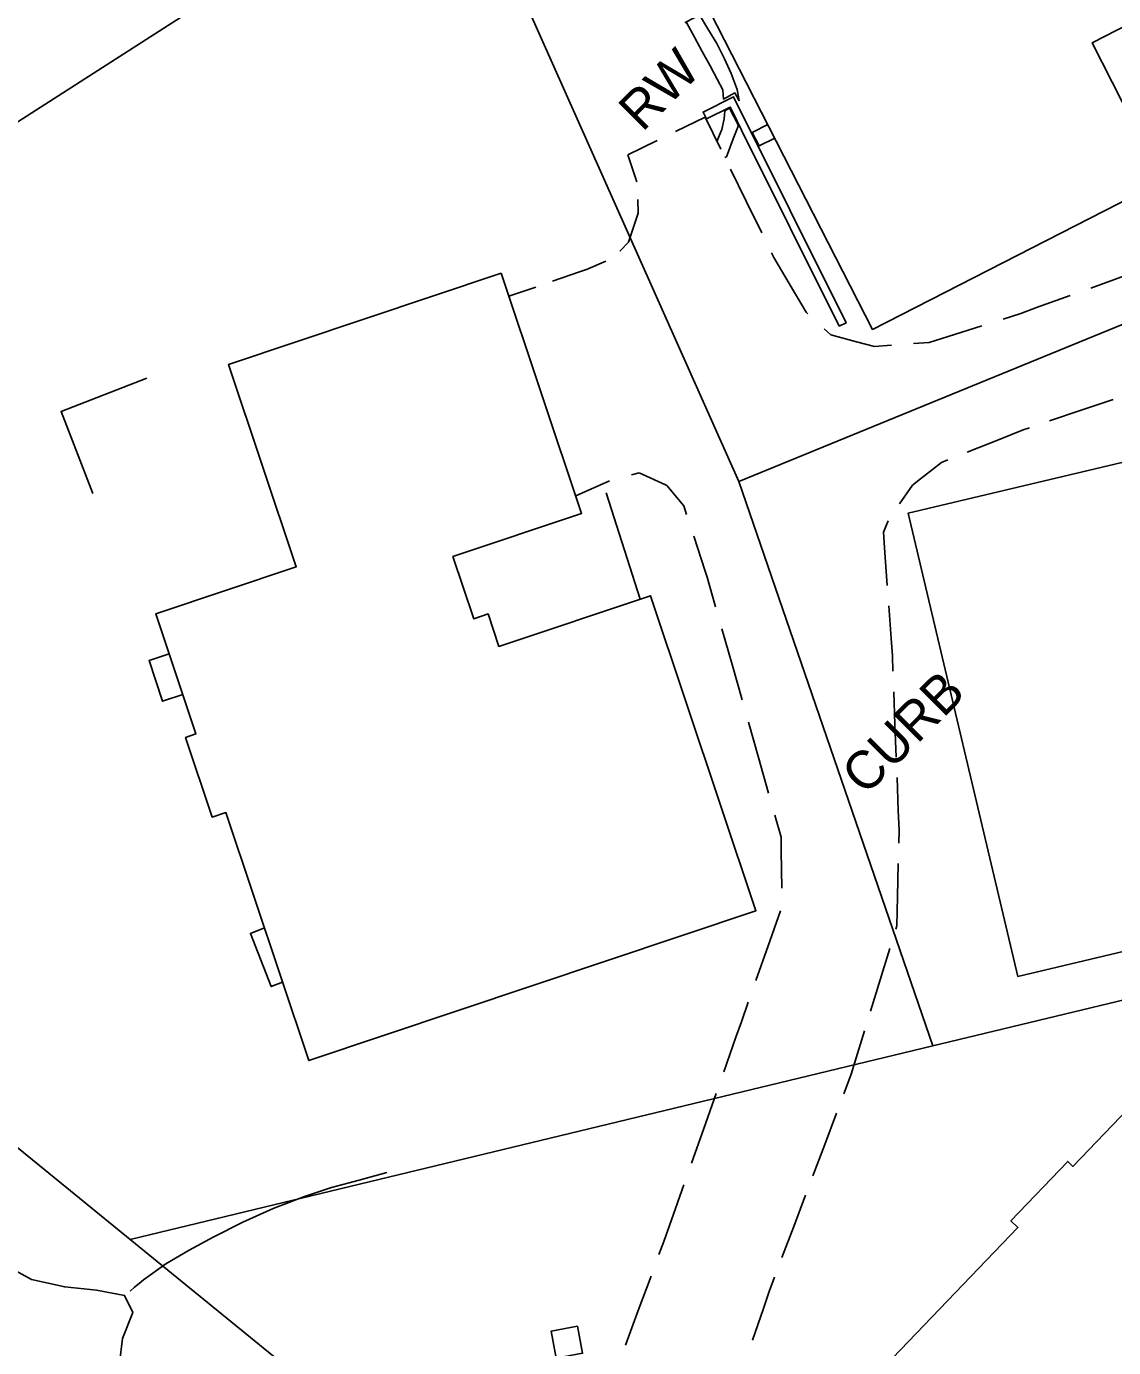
# Model space of a CAD drawing. Extents: x 2443269 to 2494951, y 591171 to 622130.
# Drawn here: x 2462063.7 to 2462180.8, y 603685.7 to 603828 of the extents above; entities that cross this region are included whole.
import ezdxf

# ---------------------------------------------------------------- set-up
doc = ezdxf.new("R2010")
doc.units = 0
for name, color, linetype in [('SURVEY - DRAINAGE - Natural Features', 7, 'Continuous'), ('SURVEY - NON-TRANSPORTATION - Buildings', 7, 'Continuous'), ('SURVEY - NON-TRANSPORTATION - Features', 7, 'Continuous'), ('SURVEY - NON-TRANSPORTATION - Features Text', 7, 'Continuous'), ('SURVEY - PROPERTY - Property Lines', 7, 'Continuous'), ('SURVEY - TRANSPORTATION - Features', 7, 'Continuous'), ('SURVEY - TRANSPORTATION - Features Text', 7, 'Continuous')]:
    doc.layers.add(name, color=color, linetype=linetype)

msp = doc.modelspace()

# ---------------------------------------------------------------- linework, layer by layer
at = {"layer": 'SURVEY - DRAINAGE - Natural Features'}
for points in [[(2462102.49, 603704.548), (2462099.514, 603703.727), (2462096.542, 603702.904), (2462093.612, 603701.962), (2462090.266, 603700.657), (2462086.981, 603699.19), (2462083.776, 603697.569), (2462081.194, 603696.175), (2462078.668, 603694.679), (2462076.279, 603692.989), (2462075.791, 603692.589), (2462075.308, 603692.176), (2462074.826, 603691.766)], [(2462073.688, 603684.01), (2462074.016, 603686.644), (2462075.115, 603689.466), (2462074.226, 603691.3), (2462071.204, 603691.861), (2462067.785, 603692.205), (2462064.209, 603693.025), (2462061.476, 603694.508)]]:
    msp.add_lwpolyline(points, dxfattribs=at)
at = {"layer": 'SURVEY - NON-TRANSPORTATION - Buildings'}
for points in [[(2462189.731, 603883.675), (2462200.446, 603862.74), (2462202.273, 603863.675), (2462218.467, 603832.031), (2462194.373, 603819.698), (2462187.585, 603832.963), (2462181.614, 603829.905), (2462182.464, 603828.248), (2462178.52, 603826.231), (2462186.132, 603811.358), (2462154.875, 603795.361), (2462131.712, 603840.624), (2462171.443, 603860.958), (2462169.124, 603865.489), (2462174.439, 603868.209), (2462171.342, 603874.262)], [(2462114.836, 603801.434), (2462123.504, 603775.538), (2462109.632, 603770.896), (2462111.873, 603764.197), (2462113.418, 603764.715), (2462114.593, 603761.211), (2462130.932, 603766.68), (2462142.296, 603732.733), (2462094.091, 603716.598), (2462085.151, 603743.307), (2462083.688, 603742.819), (2462080.81, 603751.411), (2462081.926, 603751.785), (2462077.595, 603764.721), (2462092.743, 603769.79), (2462085.443, 603791.595)], [(2462230.987, 603788.547), (2462239.091, 603754.347), (2462226.033, 603751.254), (2462225.085, 603755.25), (2462216.62, 603753.245), (2462220.292, 603737.746), (2462206.358, 603734.446), (2462206.588, 603733.478), (2462198.533, 603731.569), (2462198.369, 603732.258), (2462170.511, 603725.657), (2462158.691, 603775.558), (2462192.798, 603783.639), (2462196.712, 603767.12), (2462200.472, 603768.012), (2462200.912, 603766.158), (2462207.877, 603767.809), (2462204.452, 603782.261)], [(2462187.359, 603669.479), (2462197.739, 603659.525), (2462178.95, 603639.925), (2462145.236, 603672.248), (2462170.525, 603698.626), (2462169.783, 603699.338), (2462175.912, 603705.732), (2462176.469, 603705.197), (2462196.092, 603725.663), (2462232.851, 603690.424), (2462208.438, 603664.958), (2462196.072, 603676.812), (2462193.297, 603673.915), (2462192.418, 603674.758), (2462188.553, 603670.726)]]:
    msp.add_lwpolyline(points, close=True, dxfattribs=at)
at = {"layer": 'SURVEY - NON-TRANSPORTATION - Features'}
for p, q in [((2462143.573, 603817.444), (2462141.903, 603816.595)), ((2462129.809, 603766.306), (2462126.132, 603777.766))]:
    msp.add_line(p, q, dxfattribs=at)
for points in [[(2462140.475, 603820.007), (2462140.016, 603820.85), (2462138.779, 603820.177), (2462138.737, 603821.194), (2462138.126, 603822.32), (2462137.346, 603823.757), (2462136.502, 603825.309), (2462135.653, 603826.87), (2462134.806, 603828.429), (2462134.665, 603828.422), (2462135.643, 603828.954), (2462136.217, 603829.265)], [(2462140.475, 603820.007), (2462140.262, 603821.201), (2462139.616, 603822.927), (2462138.907, 603824.508), (2462138.064, 603826.171), (2462137.122, 603827.743), (2462136.217, 603829.265)], [(2462151.273, 603795.702), (2462152.008, 603796.067), (2462139.885, 603820.42), (2462136.588, 603818.78), (2462136.591, 603818.78), (2462136.955, 603818.045)], [(2462139.793, 603818.763), (2462139.517, 603819.321), (2462136.955, 603818.045)], [(2462138.077, 603815.633), (2462138.632, 603816.893), (2462138.871, 603818.051), (2462138.937, 603818.931)], [(2462138.933, 603813.888), (2462139.107, 603813.977), (2462139.842, 603815.889), (2462140.118, 603816.608), (2462140.397, 603817.336), (2462139.458, 603819.193), (2462138.937, 603818.931)], [(2462151.273, 603795.702), (2462140.751, 603816.844), (2462139.796, 603818.763)], [(2462144.321, 603815.988), (2462142.647, 603815.135), (2462141.903, 603816.595)], [(2462070.823, 603777.704), (2462067.385, 603786.516), (2462076.624, 603790.122)], [(2462080.505, 603756.027), (2462078.323, 603755.309), (2462076.87, 603759.715), (2462079.032, 603760.427)], [(2462089.308, 603730.883), (2462087.798, 603730.296), (2462090.036, 603724.557), (2462091.266, 603725.036)]]:
    msp.add_lwpolyline(points, dxfattribs=at)
msp.add_lwpolyline([(2462123.064, 603687.963), (2462123.609, 603685.056), (2462120.748, 603684.521), (2462120.203, 603687.428)], close=True, dxfattribs=at)
at = {"layer": 'SURVEY - PROPERTY - Property Lines'}
for p, q in [((2462140.436, 603778.987), (2462246.951, 603822.526)), ((2462161.36, 603718.186), (2462257.076, 603741.267))]:
    msp.add_line(p, q, dxfattribs=at)
for points in [[(2462025.308, 603793.784), (2462109.744, 603847.901), (2462140.436, 603778.987), (2462161.36, 603718.186), (2462074.84, 603697.323), (2462035.251, 603729.555)], [(2462074.84, 603697.323), (2462108.146, 603670.206), (2462105.827, 603654.627), (2462180.839, 603577.89)]]:
    msp.add_lwpolyline(points, dxfattribs=at)
at = {"layer": 'SURVEY - TRANSPORTATION - Features'}
for p, q in [((2462133.631, 603816.683), (2462136.804, 603818.222)), ((2462136.804, 603818.222), (2462138.492, 603814.786)), ((2462136.804, 603818.222), (2462136.804, 603818.222)), ((2462128.474, 603814.183), (2462131.648, 603815.722)), ((2462129.439, 603811.279), (2462128.474, 603814.183)), ((2462128.474, 603814.183), (2462128.474, 603814.183)), ((2462139.547, 603812.639), (2462141.235, 603809.203)), ((2462129.596, 603807.887), (2462129.549, 603809.376)), ((2462141.235, 603809.203), (2462142.924, 603805.767)), ((2462129.102, 603806.396), (2462129.596, 603807.887)), ((2462128.566, 603804.777), (2462129.102, 603806.396)), ((2462127.622, 603803.804), (2462128.566, 603804.777)), ((2462124.012, 603801.831), (2462126.102, 603802.707)), ((2462143.979, 603803.619), (2462144.222, 603803.124)), ((2462144.222, 603803.124), (2462145.886, 603800.301)), ((2462120.37, 603800.566), (2462123.262, 603801.57)), ((2462123.262, 603801.57), (2462124.012, 603801.831)), ((2462178.407, 603799.826), (2462182.008, 603801.125)), ((2462115.672, 603798.934), (2462118.563, 603799.938)), ((2462145.886, 603800.301), (2462147.706, 603797.212)), ((2462172.555, 603797.714), (2462176.156, 603799.014)), ((2462147.706, 603797.212), (2462147.885, 603797.049)), ((2462168.929, 603796.489), (2462170.843, 603797.097)), ((2462170.843, 603797.097), (2462172.555, 603797.714)), ((2462149.654, 603795.438), (2462150.351, 603794.803)), ((2462163, 603794.606), (2462166.648, 603795.765)), ((2462150.351, 603794.803), (2462153.137, 603794.048)), ((2462153.137, 603794.048), (2462155.072, 603793.524)), ((2462159.276, 603793.835), (2462160.964, 603793.96)), ((2462160.964, 603793.96), (2462163, 603794.606)), ((2462155.072, 603793.524), (2462156.89, 603793.659)), ((2462180.792, 603787.818), (2462177.366, 603786.661)), ((2462177.366, 603786.661), (2462173.941, 603785.504)), ((2462171.099, 603784.544), (2462168.428, 603783.479)), ((2462171.8, 603784.781), (2462171.099, 603784.544)), ((2462168.428, 603783.479), (2462165.07, 603782.14)), ((2462162.971, 603781.303), (2462162.303, 603781.037)), ((2462129.714, 603779.935), (2462128.889, 603779.718)), ((2462132.55, 603778.628), (2462129.714, 603779.935)), ((2462162.303, 603781.037), (2462160.019, 603779.256)), ((2462126.495, 603779.063), (2462122.867, 603777.438)), ((2462132.69, 603778.563), (2462132.55, 603778.628)), ((2462134.514, 603776.345), (2462132.69, 603778.563)), ((2462159.153, 603778.58), (2462157.779, 603776.571)), ((2462160.019, 603779.256), (2462159.153, 603778.58)), ((2462160.019, 603779.256), (2462160.019, 603779.256)), ((2462134.811, 603775.444), (2462134.514, 603776.345)), ((2462156.561, 603774.734), (2462156.03, 603773.511)), ((2462136.833, 603769.309), (2462135.589, 603773.084)), ((2462156.03, 603773.511), (2462156.19, 603771.318)), ((2462156.19, 603771.318), (2462156.447, 603767.796)), ((2462137.044, 603768.668), (2462136.833, 603769.309)), ((2462137.947, 603765.493), (2462137.044, 603768.668)), ((2462156.608, 603765.594), (2462156.865, 603762.072)), ((2462139.714, 603759.28), (2462138.626, 603763.104)), ((2462156.865, 603762.072), (2462157.001, 603760.21)), ((2462157.001, 603760.21), (2462157.064, 603758.546)), ((2462140.801, 603755.456), (2462139.714, 603759.28)), ((2462157.148, 603756.34), (2462157.283, 603752.811)), ((2462142.568, 603749.243), (2462141.481, 603753.067)), ((2462157.283, 603752.811), (2462157.417, 603749.281)), ((2462143.655, 603745.42), (2462142.568, 603749.243)), ((2462157.501, 603747.075), (2462157.636, 603743.546)), ((2462145.006, 603740.67), (2462144.335, 603743.03)), ((2462157.636, 603743.546), (2462157.716, 603741.431)), ((2462157.716, 603741.431), (2462157.685, 603740.016)), ((2462145.025, 603739.148), (2462145.006, 603740.67)), ((2462145.074, 603735.174), (2462145.025, 603739.148)), ((2462157.637, 603737.809), (2462157.559, 603734.278)), ((2462157.559, 603734.278), (2462157.49, 603731.116)), ((2462143.613, 603728.968), (2462144.934, 603732.717)), ((2462157.49, 603731.116), (2462157.381, 603730.763)), ((2462142.291, 603725.219), (2462143.613, 603728.968)), ((2462156.731, 603728.654), (2462155.692, 603725.278)), ((2462155.692, 603725.278), (2462154.652, 603721.903)), ((2462140.728, 603720.785), (2462141.465, 603722.876)), ((2462140.142, 603719.127), (2462140.728, 603720.785)), ((2462138.818, 603715.38), (2462140.142, 603719.127)), ((2462154.002, 603719.793), (2462152.962, 603716.418)), ((2462152.962, 603716.418), (2462152.562, 603715.115)), ((2462152.962, 603716.418), (2462152.962, 603716.418)), ((2462152.562, 603715.115), (2462151.772, 603713.025)), ((2462136.665, 603709.289), (2462137.99, 603713.037)), ((2462150.978, 603710.923), (2462149.707, 603707.558)), ((2462135.34, 603705.541), (2462136.665, 603709.289)), ((2462149.707, 603707.558), (2462148.436, 603704.194)), ((2462133.187, 603699.451), (2462134.512, 603703.199)), ((2462147.641, 603702.091), (2462146.37, 603698.726)), ((2462132.359, 603697.107), (2462133.187, 603699.451)), ((2462146.37, 603698.726), (2462145.099, 603695.362)), ((2462131.843, 603695.71), (2462132.359, 603697.107)), ((2462129.603, 603689.651), (2462130.981, 603693.38)), ((2462144.304, 603693.259), (2462143.72, 603691.713)), ((2462143.72, 603691.713), (2462143.095, 603689.872)), ((2462128.225, 603685.922), (2462129.603, 603689.651)), ((2462143.095, 603689.872), (2462141.939, 603686.467))]:
    msp.add_line(p, q, dxfattribs=at)

# ---------------------------------------------------------------- texts
at = {"layer": 'SURVEY - NON-TRANSPORTATION - Features Text'}
msp.add_text('RW', height=4.101, rotation=45, dxfattribs=at).set_placement((2462130.046, 603816.565))
at = {"layer": 'SURVEY - TRANSPORTATION - Features Text'}
msp.add_text('CURB', height=4.101, rotation=45, dxfattribs=at).set_placement((2462154.078, 603745.04))

doc.saveas('drawing.dxf')
